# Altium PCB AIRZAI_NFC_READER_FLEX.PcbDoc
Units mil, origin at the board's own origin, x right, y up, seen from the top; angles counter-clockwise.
Board outline 3133.86 x 5807.99 mil, 2 copper layers (Top Layer, Bottom Layer); 43 components, 43 nets, 193 pads, 82 vias.
Unrouted connection lines stored in the file: 129.
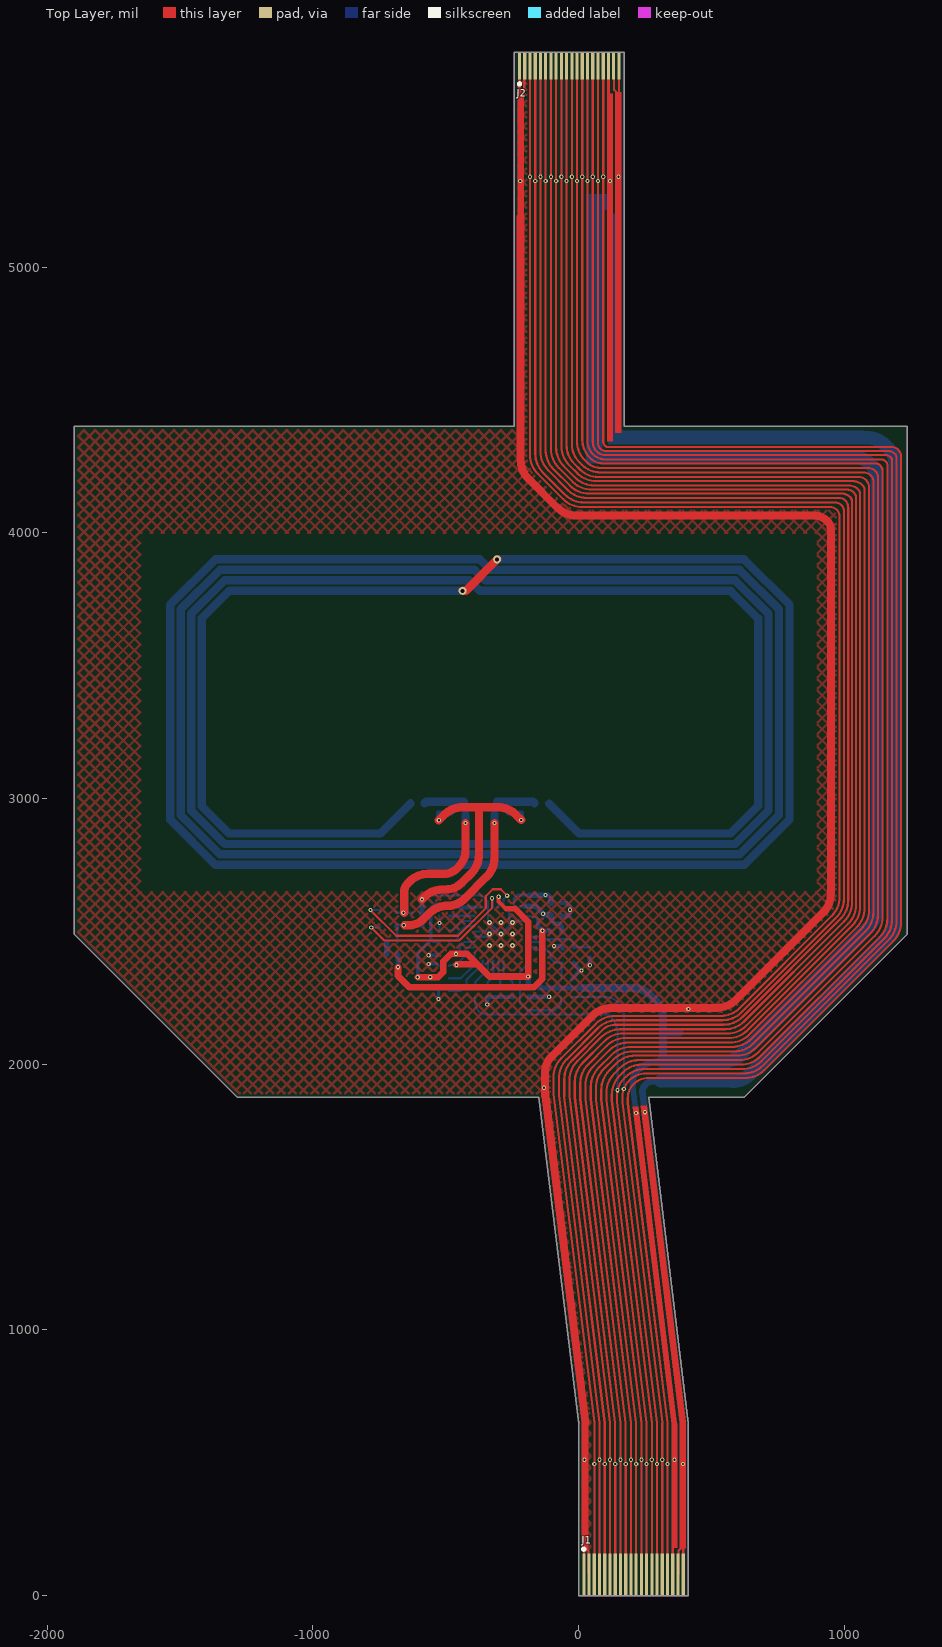
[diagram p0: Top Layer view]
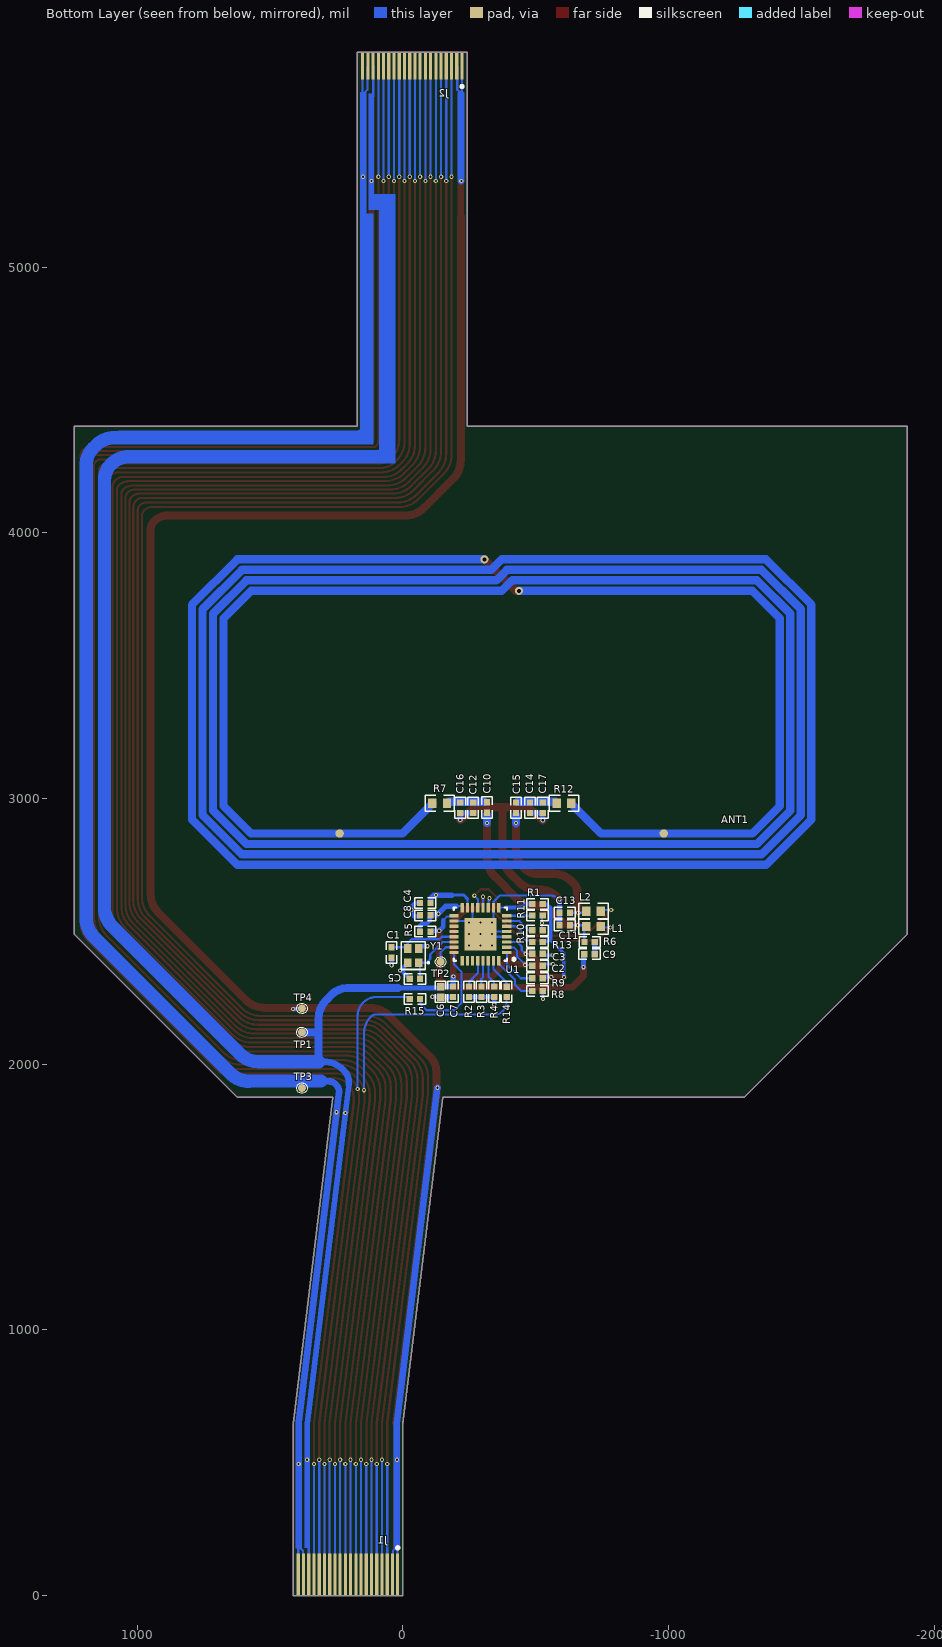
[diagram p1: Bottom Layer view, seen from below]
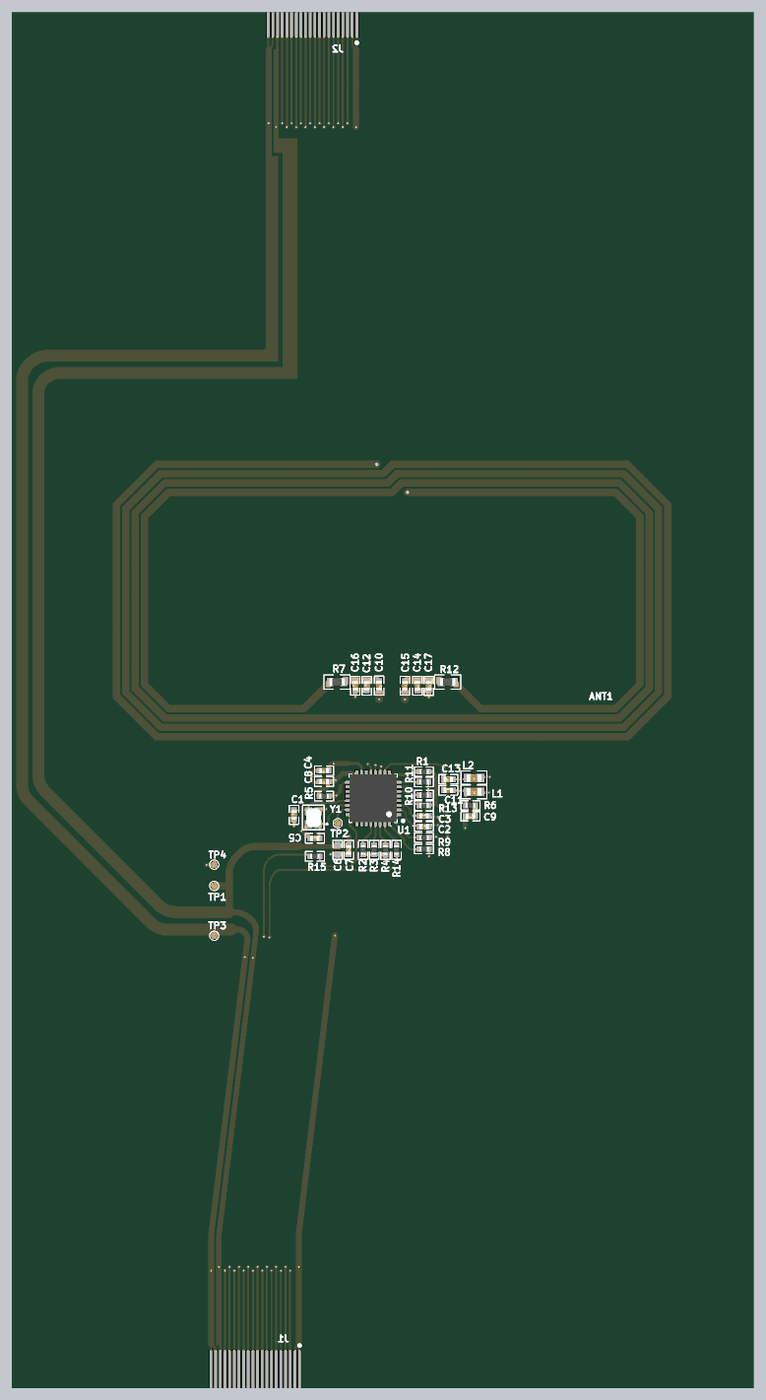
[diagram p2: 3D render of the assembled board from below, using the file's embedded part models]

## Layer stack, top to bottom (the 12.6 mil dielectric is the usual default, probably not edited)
Top Solder: solder mask 0.4, Solder Resist, Dk 3.5
Top Layer: signal copper 1.4
Dielectric 1: dielectric 12.6, FR-4, Dk 4.8
Bottom Layer: signal copper 1.4
Bottom Solder: solder mask 0.4, Solder Resist, Dk 3.5

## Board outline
-1284.09,1874.98 -149.22,1874.98 0,647.51 0,0 413.39,0 413.39,647.51 264.16,1874.98 622.68,1874.98 1236.22,2488.52 1236.22,4401.3 171.26,4401.3 171.26,5807.99 -242.13,5807.99 -242.13,4401.3 -1897.64,4401.3 -1897.64,2649.98 -1897.64,2488.52

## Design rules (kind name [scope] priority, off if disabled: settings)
Clearance Clearance_polygon_5V [OnLayer('Keep-Out Layer') vs (InNet('+5V') AND InPolygon)] p1: gap=10 ignorepadtopadclearanceinfootprint=FALSE
Clearance Clearance_POLYGON_KEEPOUT [(OnLayer('Keep-Out Layer')) vs (InNet('GND') AND InPolygon)] p2: gap=10 ignorepadtopadclearanceinfootprint=FALSE
Clearance [All] p3: gap=6 ignorepadtopadclearanceinfootprint=FALSE
MinimumSolderMaskSliver [All] p1: minsoldermaskwidth=1
PolygonConnect [All] p1: connectstyle=Direct reliefconductorwidth=10 reliefentries=4 polygonreliefangle="90 Angle" airgapwidth=10
RoomDefinition AIRZAI_NFC_READER_FLEX [InComponentClass('AIRZAI_NFC_READER_FLEX')] p1: confinementstyle=ConfineIn formatcopy=TRUE lockcomponents=FALSE outline -17037.88,-12776.19 -2377.88,-12776.19 -2377.88,-3176.19 -17037.88,-3176.19
RoutingVias [All] p1: holewidth=28 width=50 viastyle="Through Hole" minholewidth=8 minwidth=16 maxholewidth=28 maxwidth=50
SilkToSilkClearance [All] p1: silktosilkclearance=1
SilkToSolderMaskClearance [IsPad] p1: minsilkscreentomaskgap=2 clearancetoexposedcopper=TRUE
SolderMaskExpansion [All] p1: expansion=4
UnRoutedNet [All] p1: checkbadconnections=TRUE
Width [All] p1: maxlimit=100 minlimit=6 preferedwidth=10
26 further rules are at their usual default settings.

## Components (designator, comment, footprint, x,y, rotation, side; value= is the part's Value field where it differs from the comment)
ANT1 "NFC_ANT" ANTENNA-NFC-60MMX30MM -371.77,3325.02 r0 bottom
C1 "12pF" 0402CAP 43.03,2420.23 r90 bottom
C2 "0.1µF" 0402CAP -506.62,2370.7 r180 bottom
C3 "0.1µF" 0402CAP -506.62,2415.38 r180 bottom
C4 "0.1µF" 0402CAP -83.95,2606.26 r0 bottom
C5 "12pF" 0402CAP -45.06,2321.09 r180 bottom
C6 "1uF" CAPC0402(1005)60_M -141.75,2272.47 r90 bottom
C7 "0.1µF" 0402CAP -188.97,2272.34 r270 bottom
C8 "0.1µF" 0402CAP -83.95,2560.26 r0 bottom
C9 "1nF" 0402CAP -702.55,2414.09 r0 bottom
C10 "18pF" 0402CAP -316.77,2965.75 r270 bottom
C11 "220pF" 0402CAP -609.12,2523.09 r180 bottom
C12 "47pF" 0402CAP -264.47,2965.32 r90 bottom
C13 "220pF" 0402CAP -609.12,2570.09 r0 bottom
C14 "47pF" 0402CAP -478.47,2965.32 r270 bottom
C15 "18pF" 0402CAP -425.77,2965.32 r270 bottom
C16 "DNP" 0402CAP -215.9,2965.32 r90 bottom
C17 "DNP" 0402CAP -526.47,2965.01 r270 bottom
J1 "FFC Cable" FFC_PADS_MBD 196.85,78.74 r180 top locked
J2 "FFC Cable" FFC_PADS_LID -45.28,5756.81 r180 top locked
L1 "560nH" 0603CAP -717.55,2518.09 r0 bottom
L2 "560mH" 0603CAP -717.55,2576.09 r0 bottom
R1 "0R" 0402 -506.44,2602.57 r180 bottom
R2 "10K" 0402 -248.97,2272.34 r90 bottom
R3 "10K" 0402 -295.97,2272.34 r90 bottom
R4 "10K" 0402 -343.72,2272.34 r90 bottom
R5 "1K" 0402 -84.44,2498.81 r180 bottom
R6 "2.7K" 0402 -702.87,2460.09 r180 bottom
R7 "3.3" 0603 -138.47,2981.32 r180 bottom
R8 "10K" 0402 -506.66,2275.57 r180 bottom
R9 "10K" 0402 -506.66,2323.57 r180 bottom
R10 "0R" 0402 -506.63,2503.57 r180 bottom
R11 "0R" 0402 -506.44,2559.57 r180 bottom
R12 "3.3" 0603 -606.47,2981.32 r0 bottom
R13 "10K" 0402 -506.44,2459.57 r180 bottom
R14 "0R" 0402 -390.4,2272.23 r270 bottom
R15 "0R" 0402 -45.06,2245.2 r0 bottom
TP1 "WIREPT" TP_0.9MM 380,2120 r90 bottom
TP2 "WIREPT" TP_0.9MM -141.97,2385.09 r90 bottom
TP3 "WIREPT" TP_0.9MM 380,1910 r90 bottom
TP4 "WIREPT" TP_0.9MM 380,2210 r90 bottom
U1 "MFRC52202HN1,115" VFQFN-32-MFRC52202HN1,157 -291.95,2489.54 r0 bottom
Y1 "27.12MHz" XTAL_2016 -38.95,2408.23 r90 bottom

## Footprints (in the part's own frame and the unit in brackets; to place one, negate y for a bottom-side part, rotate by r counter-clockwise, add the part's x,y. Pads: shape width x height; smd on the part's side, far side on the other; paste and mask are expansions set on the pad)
0402 [mm] "Chip Resistor, Body 1.1x0.5mm, IPC High Density"
  rect 0.6x0.6 smd: 1(-0.5,0) 2(0.5,0)
  silkscreen extent -1.02,-0.51 1.02,0.51, body extent -0.5,-0.25 0.5,0.25, height 0.27
0402CAP [mm] "Chip Capacitor, Body 1.1x0.5mm, IPC High Density"
  rect 0.6x0.6 smd: 1(-0.5,0) 2(0.5,0)
  silkscreen extent -1.02,-0.51 1.02,0.51, body extent -0.5,-0.3 0.5,0.3, height 0.19
0603 [mm] "Chip Resistor, Body 1.6x0.8mm, IPC High Density"
  rect 0.8x0.9 smd: 1(-0.7,0) 2(0.7,0)
  silkscreen extent -1.4,-0.76 1.4,0.76, body extent -0.8,-0.41 0.8,0.4, height 0.37
0603CAP [mm] "Chip Capacitor, Body 1.6x0.8mm, IPC High Density"
  rect 0.8x0.9 smd: 1(-0.7,0) 2(0.7,0)
  silkscreen extent -1.4,-0.76 1.4,0.76, body extent -0.8,-0.4 0.8,0.4, height 0.29
ANTENNA-NFC-60MMX30MM [mil] "ANTENNA-ID2+10P-01"
  round 30 hole 15: 1(-65,-456.69) 2(65,-574.8)
  round 31.5 smd paste-31.5: 1(610,456.69) 2(-610,456.69)
  Top Layer lines w31.5: -610,456.69 -943.7,456.69 -1047.24,353.15 -1047.24,-353.15 -943.7,-456.69 -65,-456.69 ; 65,-574.8 994.96,-574.8 1165.35,-404.41 1165.35,404.41 994.96,574.8 -994.96,574.8 -1165.35,404.41 -1165.35,-404.41 -994.96,-574.8 0,-574.8 39.37,-535.43 977.87,-535.43 1125.98,-387.32 1125.98,387.32 977.87,535.43 -977.87,535.43 -1125.98,387.32 -1125.98,-387.32 -977.87,-535.43 -19.37,-535.43 20,-496.06 960.79,-496.06 1086.61,-370.24 1086.61,370.24 960.79,496.06 -960.79,496.06 -1086.61,370.24 -1086.61,-370.24 -960.79,-496.06 -39.37,-496.06 0,-456.69 943.7,-456.69 1047.24,-353.15 1047.24,353.15 943.7,456.69 610,456.69
  Bottom Layer lines w31.5: -65,-456.69 -53.11,-456.69 65,-574.8
CAPC0402(1005)60_M [mm] "Chip Capacitor, Body 1.0x0.5mm, Height 0.6mm, IPC Low Density"
  rect 0.72x0.72 smd: 1(-0.5,0) 2(0.5,0)
  silkscreen extent -1.02,-0.51 1.02,0.51, body extent -0.55,-0.3 0.55,0.3, height 0.6
FFC_PADS_LID [mm] "(0.50mm"
  rect 0.3x2.6 smd: 1(4.5,0) 2(4,0) 3(3.5,0) 4(3,0) 5(2.5,0) 6(2,0) 7(1.5,0) 8(1,0) 9(0.5,0) 10(0,0) 11(-0.5,0) 12(-1,0) 13(-1.5,0) 14(-2,0) 15(-2.5,0) 16(-3,0) 17(-3.5,0) 18(-4,0) 19(-4.5,0) 20(-5,0)
  rect 0.3x2.6 smd far side: 1(4.5,0) 2(4,0) 3(3.5,0) 4(3,0) 5(2.5,0) 6(2,0) 7(1.5,0) 8(1,0) 9(0.5,0) 10(0,0) 11(-0.5,0) 12(-1,0) 13(-1.5,0) 14(-2,0) 15(-2.5,0) 16(-3,0) 17(-3.5,0) 18(-4,0) 19(-4.5,0) 20(-5,0)
  silkscreen extent 4.37,1.58 4.62,1.83
FFC_PADS_MBD [mm] "(0.50mm"
  rect 0.3x4 smd: 1(4.5,0) 2(4,0) 3(3.5,0) 4(3,0) 5(2.5,0) 6(2,0) 7(1.5,0) 8(1,0) 9(0.5,0) 10(0,0) 11(-0.5,0) 12(-1,0) 13(-1.5,0) 14(-2,0) 15(-2.5,0) 16(-3,0) 17(-3.5,0) 18(-4,0) 19(-4.5,0) 20(-5,0)
  rect 0.3x4 smd far side: 1(4.5,0) 2(4,0) 3(3.5,0) 4(3,0) 5(2.5,0) 6(2,0) 7(1.5,0) 8(1,0) 9(0.5,0) 10(0,0) 11(-0.5,0) 12(-1,0) 13(-1.5,0) 14(-2,0) 15(-2.5,0) 16(-3,0) 17(-3.5,0) 18(-4,0) 19(-4.5,0) 20(-5,0)
  silkscreen extent 4.39,-2.56 4.64,-2.31
TP_0.9MM [mm] "0.9MM DIA TESTPOINT"
  round 0.75 smd paste-5 mask+0.05: 1(0,0)
  silkscreen extent -0.5,-0.5 0.5,0.5
VFQFN-32-MFRC52202HN1,157 [mm]
  rect 0.9x0.31 smd: 1(-2.529,1.75) 2(-2.529,1.25) 3(-2.529,0.75) 4(-2.529,0.25) 5(-2.529,-0.25) 6(-2.529,-0.75) 7(-2.529,-1.25) 8(-2.529,-1.75) 17(2.529,-1.75) 18(2.529,-1.25) 19(2.529,-0.75) 20(2.529,-0.25) 21(2.529,0.25) 22(2.529,0.75) 23(2.529,1.25) 24(2.529,1.75)
  rect 0.31x0.9 smd: 9(-1.75,-2.529) 10(-1.25,-2.529) 11(-0.75,-2.529) 12(-0.25,-2.529) 13(0.25,-2.529) 14(0.75,-2.529) 15(1.25,-2.529) 16(1.75,-2.529) 25(1.75,2.529) 26(1.25,2.529) 27(0.75,2.529) 28(0.25,2.529) 29(-0.25,2.529) 30(-0.75,2.529) 31(-1.25,2.529) 32(-1.75,2.529)
  rect 3.1x3.1 smd: 33(0,0)
  silkscreen extent -3.32,-2.55 2.55,2.55, body extent -2.55,-2.55 2.55,2.55, height 1
XTAL_2016 [mm] "2.00mm x 1.60mm"
  rect 0.85x0.75 smd: 1(-0.675,-0.525) 2(0.675,-0.525) 3(0.675,0.525) 4(-0.675,0.525)
  silkscreen extent -1.32,-1.47 1.32,1.14, body extent -1,-0.81 1,0.79, height 0.65

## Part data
C1 C5: library part CAP, "CAP CER 12PF 50V C0G/NP0 0402", Case/Package=0402, Case Code (Metric)=1005, Dielectric=C0G, Dielectric Material=Ceramic, Manufacturer=KEMET, Manufacturer Part Number=C0402C120J5GACTU, Max Operating Temperature=125°C, Min Operating Temperature=-55°C, Package Quantity=1, Supplier Part Number 1=399-1013-6-ND, Temperature Coefficient=30ppm/°C, Tolerance=5%, Voltage=50V
C2 C3 C4 C7 C8: library part C0402-100n, "Capacitor, X7R, ±10%", Case-EIA=0402, Case-Metric=1005, Manufacturer=TDK, Manufacturer Part Number=C1005X7R1C104K, Rated Voltage="16 V", Supplier Part Number 1=445-4952-2-ND, Tolerance=±20%
C6: library part CAP, "CAP 1uF 16V ±10% 0402 (1005 Metric) Thickness 0.6mm SMD", Case/Package=0402, Case Code (Metric)=1005, Dielectric=X5R, Manufacturer="Taiyo Yuden", Manufacturer Part Number=EMK105BJ105KV-F, Max Operating Temperature=85°C, Min Operating Temperature=-55°C, Package Quantity=1, Supplier Part Number 1=587-2477-6-ND, Tolerance=10%, Voltage Rating=16V
C9: library part 56p, "CAP CER 1000PF 50V C0G/NP0 0402", Case/Package=0402, Case Code (Metric)=1005, Dielectric=C0G, Manufacturer=Murata, Manufacturer Part Number=GRM1555C1H102FA01D, Max Operating Temperature=125°C, Min Operating Temperature=-55°C, Package Quantity=1, Supplier Part Number 1=490-6189-1-ND, Tolerance=1%, Voltage=50V
C10 C15: library part 56p, "CAP CER 18PF 50V NP0 0402", Case/Package=0402, Case Code (Metric)=1005, Dielectric=C0G, Manufacturer="Kyocera AVX", Manufacturer Part Number=04025U180FAT2A, Max Operating Temperature=125°C, Min Operating Temperature=-55°C, Package Quantity=10000, Supplier Part Number 1=478-10144-1-ND, Tolerance=1%, Voltage Rating=50V
C11 C13: library part 56p, "CAP CER 220PF 50V NPO 0402", Case/Package=0402, Case Code (Metric)=1005, Dielectric=C0G, Manufacturer=Yageo, Manufacturer Part Number=CC0402FRNPO9BN221, Max Operating Temperature=125°C, Min Operating Temperature=-55°C, Supplier Part Number 1=311-3730-1-ND, Tolerance=1%, Voltage Rating=50V
C12 C14: library part 56p, "CAP CER 47PF 50V C0G/NP0 0402", Dielectric=C0G, Manufacturer=Murata, Manufacturer Part Number=GJM1555C1H470FB01D, Supplier Part Number 1=490-16376-1-ND, Tolerance=1%, Voltage Rating (DC)=50V
C16 C17: library part 56p
J1 J2: library part XF2M-2015-1A-R100, "Cable"
L1: library part Inductor, "FIXED IND 560NH 100MA 1.05 OHM", Case/Package=0603, Case Code (Metric)=1608, Current Rating=100mA, DC Resistance (DCR)=1.05R, Manufacturer=TDK, Manufacturer Part Number=MLF1608DR56JTD25, Max DC Current=30mA, Max Operating Temperature=125°C, Min Operating Temperature=-55°C, Package Quantity=4000, Ratings=AEC-Q200, Self Resonant Frequency=170MHz, Supplier Part Number 1=445-16970-1-ND, Test Frequency=25MHz, Tolerance=5%
L2: library part Inductor, "FIXED IND 560NH 100MA 1.05 OHM", Case/Package=0603, Case Code (Metric)=1608, Current Rating=100mA, DC Resistance (DCR)=1.05R, Inductance=560nH, Manufacturer=TDK, Manufacturer Part Number=MLF1608DR56JTD25, Max DC Current=30mA, Max Operating Temperature=125°C, Min Operating Temperature=-55°C, Package Quantity=4000, Ratings=AEC-Q200, Self Resonant Frequency=170MHz, Supplier Part Number 1=445-16970-1-ND, Test Frequency=25MHz, Tolerance=5%
R1 R10 R11 R14 R15: library part R0402-12k, "Resistor, ±1%, 0.063W", Case-EIA=0402, Case-Metric=1005, Manufacturer=Panasonic, Manufacturer Part Number=ERJ-2GE0R00X, Supplier Part Number 1=P0.0JTR-ND, Tolerance=±5%
R2 R3 R4 R8 R9 R13: library part R0402-12k, "Resistor 10K, ±1%, 0.063W", Case/Package=0402, Case Code (Metric)=1005, Manufacturer="Vishay Dale", Manufacturer Part Number=CRCW040210K0JNED, Max Operating Temperature=155°C, Max Power Dissipation=63mW, Min Operating Temperature=-55°C, Package Quantity=1, Resistance=10kR, Supplier Part Number 1=541-10KJDKR-ND, Temperature Coefficient=200ppm/°C, Tolerance=5%, Voltage Rating=50V
R5: library part R0402-12k, "RES SMD 1K OHM 1% 1/16W 0402", Case/Package=0402, Case Code (Metric)=1005, Manufacturer=Yageo, Manufacturer Part Number=RC0402FR-071KL, Max Operating Temperature=155°C, Min Operating Temperature=-55°C, Power Rating=62.5mW, Resistance=1kR, Supplier Part Number 1=311-1.00KLRCT-ND, Temperature Coefficient=100ppm/°C, Tolerance=1%, Voltage Rating=50V
R6: library part R0402-12k, "RES SMD 2.7K OHM 1% 1/16W 0402", Case/Package=0402, Manufacturer="Yageo Phycomp", Manufacturer Part Number=RC0402FR-072K7L, Max Operating Temperature=155°C, Min Operating Temperature=-55°C, Power Rating=63mW, Resistance=2.7kR, Supplier Part Number 1=311-2.70KLRCT-ND, Temperature Coefficient=100ppm/°C, Tolerance=1%, Voltage Rating (DC)=50V
R7 R12: library part R0402-12k, "RES SMD 3.3 OHM 1% 1/10W 0603", Case/Package=0603, Manufacturer=Yageo, Manufacturer Part Number=AC0603FR-073R3L, Max Operating Temperature=155°C, Max Power Dissipation=100mW, Min Operating Temperature=-55°C, Resistance=3.3R, Supplier Part Number 1=YAG5335CT-ND, Temperature Coefficient=200ppm/°C, Tolerance=1%
U1: library part MFRC52201HN1,157, "IC RFID READER 13.56MHZ 32HVQFN", Frequency=13.56MHz, Manufacturer="NXP Semiconductors", Max Operating Temperature=85°C, Min Operating Temperature=-25°C, Package Quantity=1500, Supplier Part Number 1=568-15200-1-ND
Y1: library part ZTB_2, "CRYSTAL 27.12MHZ 10PF SMD", Manufacturer="ECS International", Manufacturer Part Number=ECS-271.2-10-37-CKM-TR, Supplier Part Number 1=XC2511DKR-ND

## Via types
v1: diameter 16, hole 8, Top Layer to Bottom Layer, tented both sides, 73 vias
v2: diameter 19.68, hole 8, Top Layer to Bottom Layer, 9 vias

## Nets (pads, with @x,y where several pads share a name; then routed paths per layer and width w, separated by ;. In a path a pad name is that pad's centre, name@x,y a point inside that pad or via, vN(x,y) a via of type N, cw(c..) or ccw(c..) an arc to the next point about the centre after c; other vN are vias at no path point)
3V3: C2.1 C3.1 C4.1 C6.2 C7.1 J1.18 J2.18 R1.2 R9.2 R13.2 TP1.1 U1.2 U1.3 U1.12 U1.15 | length 6922
  Top Layer w10: 112.1,5644.23 112.2,5644.33 J2.18@112.2,5756.81 ; 354.23,191.32 354.33,191.22 J1.18@354.33,78.74
  Top Layer w15: v1(-301.02,2630.32) -301.02,2612.57 -273.23,2584.78
  Top Layer w20: -273.23,2584.78 -238.41,2584.78
  Top Layer w25: v1@-606,2327.59 -528.25,2327.59 -509.44,2346.39 -509.44,2386.44 -480.5,2415.38 v1(-461.44,2415.38) -420.42,2415.38 -380.52,2375.48 ; v1(-459.94,2373.88) -458.34,2375.48 -380.52,2375.48 ; -238.41,2584.78 -189.97,2536.34 v1(-189.97,2329.78) -334.83,2329.78 -380.52,2375.48
  Bottom Layer w8: C2.1 -483.76,2373.88 v1(-459.94,2373.88) -429.97,2403.84 -429.97,2427.09 -417.24,2439.82 -392.02,2439.82 U1.2 ; C3.1 v1(-461.44,2415.38) -447.44,2429.38 -447.44,2443.09 -430.51,2460.01 U1.3 ; U1.12 -301.02,2589.88 v1(-301.02,2630.32) ; U1.15 -242.74,2620.78
  Bottom Layer w10: 112.1,5644.23 112.2,5644.33 J2.18@112.2,5756.81 ; 354.23,191.32 354.33,191.22 J1.18@354.33,78.74
  Bottom Layer w12: -242.74,2620.78 -242.74,2623.02 -228.97,2636.78 -183.97,2636.78
  Bottom Layer w13: v1(-606,2327) -606,2417 -556.77,2466.23 -556.77,2471.32 ; R13.2 -528.87,2462.32 -547.77,2462.32 -556.77,2471.32 ; R1.2 -541.87,2602.57 -556.77,2587.67 -556.77,2471.32
  Bottom Layer w15: v1(-558.44,2327.59) -530.36,2327.59 R9.2
  Bottom Layer w20: v1(-189.97,2329.78) -189.97,2293.03 C7.1 -141.88,2292.03 C6.2 ; -183.97,2636.78 -183.58,2636.39 -116.44,2636.39 -104.44,2624.39 -104.44,2607.06 C4.1
  Bottom Layer w25: 203.23,1922.32 203.23,1931.87 cw(c264.68,1931.87) 221.23,1975.32 225.94,1980.03 cw(c296.65,1909.32) 296.65,2009.32 317.23,2009.32
  Bottom Layer w30: 19,2286.32 209.28,2286.32 cw(c209.28,2203.28) 268,2262 287.94,2242.06 cw(c217.23,2171.35) 317.23,2171.35 317.23,2117 ; 317.23,2009.32 317.23,2117 ; TP1.1 320.23,2120 317.23,2117
  Bottom Layer w50: 57.23,4286.32 1029.22,4286.32 cw(c1029.22,4187.31) 1099.23,4257.32 cw(c1041.29,4199.38) 1123.23,4199.38 1123.23,2589.74 cw(c1023.23,2589.74) 1093.94,2519.03 613.52,2038.61 cw(c542.81,2109.32) 542.81,2009.32 317.23,2009.32
  other v1: 360.43,511.32 216.54,1816.32 -124.83,2636.39 118.3,5324.23
+5: J1.19 J1.20 J2.19 J2.20 TP3.1 | length 4943.7
  Top Layer w8: J2.19@131.89,5756.81 133.67,5755.03 133.67,5667.13 151.57,5649.23 J2.20@151.57,5756.81 ; J1.19@374.02,78.74 375.8,80.52 375.8,168.42 393.7,186.32 J1.20@393.7,78.74
  Bottom Layer w8: J2.19@131.89,5756.81 133.67,5755.03 133.67,5667.13 151.57,5649.23 J2.20@151.57,5756.81 ; J1.19@374.02,78.74 375.8,80.52 375.8,168.42 393.7,186.32 J1.20@393.7,78.74
  Bottom Layer w25: 239.23,1892.32 cw(c282.68,1892.32) 251.96,1923.05 254.23,1925.32 cw(c278.37,1901.18) 278.37,1935.32 309.23,1936.32
  Bottom Layer w40: 155.1,4371.32 ccw(c186.49,4402.71) 186.49,4358.32 ; 1155.52,4329.03 1165.23,4319.32
  Bottom Layer w50: 186.49,4358.32 1084.81,4358.32 cw(c1084.81,4258.32) 1155.52,4329.03 ; 309.23,1936.32 577.81,1935.32 ccw(c577.81,2035.32) 648.52,1964.61 1162.94,2479.03 ccw(c1092.23,2549.74) 1192.23,2549.74 1192.23,4254.14 ccw(c1100.04,4254.14) 1165.23,4319.32
  other v1: 392.43,495.32 250.23,1819.32 150.3,5340.23
ACCELERO_INT: J1.14 J2.14 | length 8322.1
  Top Layer w8: J2.14@33.46,5756.81 33.46,4345.45 ccw(c104.36,4345.45) 54.23,4295.32 ccw(c100.1,4341.19) 100.1,4276.32 1136.91,4276.32 cw(c1136.91,4249.01) 1156.23,4268.32 cw(c1141.74,4253.84) 1162.23,4253.84 1162.23,4098.32 1162.23,2548.74 cw(c1062.23,2548.74) 1132.94,2478.03 682.52,2027.61 cw(c611.81,2098.32) 611.81,1998.32 237.65,1998.32 ccw(c237.65,1898.32) 166.94,1969.03 154.13,1956.22 ccw(c224.84,1885.51) 124.84,1885.51 124.84,1864.77 275.59,649.15 J1.14@275.59,78.74
  Bottom Layer w8: v1@33.46,5324.23 J2.14@33.46,5756.81 ; J1.14@275.59,78.74 v1@275.59,511.32
  other v1: 275.23,511.32 33.1,5324.23
ADC_CH1: J1.5 J2.5 | length 8284.9
  Top Layer w8: J2.5@-143.7,5756.81 -143.7,4305.67 ccw(c-43.7,4305.67) -114.41,4234.96 -40.06,4160.61 ccw(c30.65,4231.32) 30.65,4131.32 981.5,4131.32 cw(c981.5,4100.59) 1003.23,4122.32 cw(c974.96,4094.05) 1014.94,4094.05 1014.94,4039.32 1014.94,2617.45 cw(c914.94,2617.45) 985.65,2546.74 616.52,2177.61 cw(c545.81,2248.32) 545.81,2148.32 136.1,2148.32 ccw(c136.1,2083.45) 90.23,2129.32 -25.05,2014.05 ccw(c45.67,1943.34) -54.33,1943.34 -54.33,1879.38 98.23,649.15 v1(98.23,495.32) ; J1.5@98.43,78.74 v1@98.43,495.32
  Bottom Layer w8: v1@-143.7,5340.23 J2.5@-143.7,5756.81 ; J1.5@98.43,78.74 v1@98.43,495.32
  other v1: -143.9,5340.23
CAP1_TOUCH_OUT: J1.7 J2.7 | length 8281.2
  Top Layer w8: J2.7@-104.33,5756.81 v1(-104.33,5340.23) -104.33,4315.3 ccw(c-4.33,4315.3) -75.04,4244.59 -22.06,4191.61 ccw(c48.65,4262.32) 48.65,4162.32 1009.67,4162.32 cw(c1009.67,4124.77) 1036.23,4151.32 cw(c1016.91,4132.01) 1044.23,4132.01 1044.23,4098.32 1044.23,2599.74 cw(c944.23,2599.74) 1014.94,2529.03 630.52,2144.61 cw(c559.81,2215.32) 559.81,2115.32 167.27,2115.32 ccw(c167.27,2015.32) 96.56,2086.03 14.68,2004.16 ccw(c85.39,1933.45) -14.61,1933.45 -14.61,1876.49 137.6,649.15 v1@137.6,495.32 ; J1.7@137.8,78.74 v1(137.8,495.32)
  Bottom Layer w8: v1(-104.33,5340.23) J2.7@-104.33,5756.81 ; J1.7@137.8,78.74 v1(137.8,495.32)
CAP2_TOUCH_OUT: J1.8 J2.8 | length 8307
  Top Layer w8: J2.8@-84.65,5756.81 v1(-84.65,5324.23) -84.65,4321.62 ccw(c15.35,4321.62) -55.36,4250.91 -12.06,4207.61 ccw(c58.65,4278.32) 58.65,4178.32 1016.02,4178.32 cw(c1016.02,4127.11) 1052.23,4163.32 cw(c1035.33,4146.42) 1059.23,4146.42 1059.23,4098.32 1059.23,2592.74 cw(c959.23,2592.74) 1029.94,2522.03 635.52,2127.61 cw(c564.81,2198.32) 564.81,2098.32 176.65,2098.32 ccw(c176.65,1998.32) 105.94,2069.03 35.27,1998.36 ccw(c105.98,1927.65) 5.98,1927.65 5.98,1870.81 157.48,649.15 v1(157.48,511.32) J1.8@157.48,78.74
  Bottom Layer w8: v1(-84.65,5324.23) J2.8@-84.65,5756.81 ; J1.8@157.48,78.74 v1(157.48,511.32)
EN: J1.17 J2.17 | length 8285.8
  Top Layer w8: J2.17@92.52,5756.81 v1(92.52,5340.23) 92.52,4344.93 ccw(c118.84,4344.93) 100.21,4326.34 ccw(c107.47,4333.57) 107.47,4323.32 1178.09,4323.32 cw(c1178.09,4289.18) 1202.23,4313.32 cw(c1175.67,4286.77) 1213.23,4286.77 1213.23,4098.32 1213.23,2533.74 cw(c1113.23,2533.74) 1183.94,2463.03 698.52,1977.61 cw(c627.81,2048.32) 627.81,1948.32 264.17,1948.32 ccw(c264.17,1866.38) 206.23,1924.32 ccw(c257.71,1872.84) 184.9,1872.84 184.9,1855.03 334.45,649.15 v1@334.45,495.32 ; J1.17@334.65,78.74 v1(334.65,495.32)
  Bottom Layer w8: v1(92.52,5340.23) J2.17@92.52,5756.81 ; J1.17@334.65,78.74 v1(334.65,495.32)
GND: C1.1 C2.2 C3.2 C4.2 C5.1 C6.1 C7.2 C8.2 C11.1 C12.1 C13.2 C14.2 C16.1 C17.2 J1.1 J1.2 J2.1 J2.2 R2.1 R3.1 R4.1 R8.2 R10.2 R11.2 TP4.1 U1.4 U1.5 U1.10 U1.14 U1.18 U1.33 Y1.2 Y1.4 | length 11361.9
  Top Layer w8: -222.44,5649.23 J2.1@-222.44,5756.81 ; -218.01,5653.66 -204.54,5667.13 J2.2@-204.54,5755.03 ; J1.1@19.69,78.74 19.69,186.32 ; 24.11,181.89 37.59,168.42 J1.2@37.59,80.52
  Top Layer w25: -218.01,5189.23 -218.01,5653.66 ; 24.11,181.89 24.11,646.32
  Top Layer w30: -218.01,5189.23 -218.01,4273.98 ccw(c-118.01,4273.98) -188.72,4203.27 -80.06,4094.61 ccw(c-9.35,4165.32) -9.35,4065.32 884.12,4065.32 cw(c884.12,3990.21) 937.23,4043.32 cw(c908.26,4014.35) 949.23,4014.35 949.23,3977.32 949.23,2640.74 cw(c849.23,2640.74) 919.94,2570.03 591.52,2241.61 cw(c520.81,2312.32) 520.81,2212.32 123.65,2212.32 ccw(c123.65,2112.32) 52.94,2183.03 -103.14,2026.95 ccw(c-48.52,1972.32) -125.77,1972.32 -125.77,1881.79 ccw(c-122.36,1881.79) -124.77,1879.38
  Top Layer w31.5: v1(-589.44,2620.32) -580.54,2629.22 cw(c-512.69,2561.36) -512.69,2657.32 -501.54,2657.32 ccw(c-501.54,2746.09) -438.77,2683.32 -404.06,2718.03 ccw(c-474.77,2788.74) -374.77,2788.74 -374.77,2967.32 ; v1(-526.2,2918.32) -506.48,2938.03 cw(c-435.77,2867.32) -435.77,2967.32 ; -440.77,2967.32 -374.77,2967.32 ; v1(-215.9,2918.91) -235.03,2938.03 ccw(c-305.74,2867.32) -305.74,2967.32 -374.77,2967.32
  Bottom Layer w8: v1(-589.44,2620.32) cw(c-555.64,2586.52) -555.64,2634.32 -363.74,2634.32 -341.16,2611.75 U1.10 -341.16,2538.75 v2(-335.26,2532.85) U1.33@-301.79,2499.38 ; C2.2@-532.84,2377.23 C2.2 ; C3.2@-531.6,2410.09 C3.2 ; R10.2 ccw(c-532.44,2509.7) -523.77,2509.7 v1(-523.77,2531.32) -523.77,2557.22 R11.2 ; U1.4 U1.33@-335.26,2479.7 ; U1.5 U1.33@-301.79,2499.38 ; U1.14 -262.42,2546.56 v2(-248.65,2532.85) v2(-248.65,2532.85) ; -222.44,5649.23 J2.1@-222.44,5756.81 ; -218.9,5652.77 -204.54,5667.13 J2.2@-204.54,5755.03 ; U1.18 -242.74,2538.75 v2(-248.65,2532.85) ; J1.1@19.69,78.74 19.69,186.32 ; 23.23,182.78 37.59,168.42 J1.2@37.59,80.52 ; U1.33@-301.79,2499.38 v2(-291.95,2489.54) v2(-248.65,2532.85)
  Bottom Layer w12: v1@-558.44,2377.23 C2.2@-532.84,2377.23 ; v1@-558.44,2410.09 C3.2@-531.6,2410.09 ; v1(-527.44,2245.09) -527.44,2274.48 R8.2
  Bottom Layer w15: TP4.1 381.81,2208.19 412.81,2208.19 v1(413,2208)
  Bottom Layer w16: v1(-343.72,2224.88) R4.1 R3.1 R2.1 ; v1(-92.77,2444.32) -91.98,2443.53 -66.4,2443.53 -59.64,2436.77 Y1.2 ; C8.2 -60.96,2556.95 -42.14,2556.95 -32.77,2566.32 v1(-32.77,2581.32) -32.77,2593.31 -45.72,2606.26 C4.2 ; C5.1 5.76,2352.23 9.19,2352.23 -18.27,2379.68 Y1.4 ; v1(42.23,2372.32) 42.23,2399.74 C1.1
  Bottom Layer w18: R2.1 R2.1@-248.91,2252.72 ; C7.2 -188.91,2252.72 -141.81,2252.72 C6.1 -140.53,2254 v1(-110.91,2254)
  Bottom Layer w20: C11.1 C13.2 v1(-589.44,2620.32) ; v1(-526.2,2918.32) -526.2,2945.05 C17.2 -526.31,2945.48 -478.62,2945.48 C14.2 ; C12.1 C16.1 v1(-215.9,2918.91)
  Bottom Layer w25: v1@-218.9,5324.23 -218.9,5652.77 ; v1(-130,1911.11) 23.23,646.32 23.23,182.78
  other v1: 22.23,511.32 11.05,2352.23 -564.44,2377.23 -564.44,2410.09 -219.9,5324.23
  other v2: -335.26,2446.23 -291.95,2446.23 -248.65,2446.23 -335.26,2489.54 -248.65,2489.54 -291.95,2532.85
"LED Str CLK": J1.10 J2.10 | length 8309.6
  Top Layer w8: J2.10@-45.28,5756.81 v1(-45.28,5324.23) -45.28,4330.25 ccw(c54.72,4330.25) -15.99,4259.54 5.23,4238.32 ccw(c72.83,4305.92) 72.83,4210.32 1054.67,4210.32 cw(c1054.67,4172.77) 1081.23,4199.32 cw(c1052.26,4170.35) 1093.23,4170.35 1093.23,4144.32 1093.23,2579.74 cw(c993.23,2579.74) 1063.94,2509.03 649.52,2094.61 cw(c578.81,2165.32) 578.81,2065.32 195.65,2065.32 ccw(c195.65,1965.32) 124.94,2036.03 74.85,1985.94 ccw(c145.56,1915.23) 45.56,1915.23 45.56,1869.12 196.85,649.15 v1(196.85,511.32) J1.10@196.85,78.74
  Bottom Layer w8: v1(-45.28,5324.23) J2.10@-45.28,5756.81 ; J1.10@196.85,78.74 v1(196.85,511.32)
"LED Str DATA": J1.11 J2.11 | length 8281.2
  Top Layer w8: J2.11@-25.59,5756.81 v1(-25.59,5340.23) -25.59,4333.48 ccw(c69.39,4333.48) 2.23,4266.32 11.94,4256.61 ccw(c82.65,4327.32) 82.65,4227.32 1071.26,4227.32 cw(c1071.26,4186.35) 1100.23,4215.32 cw(c1078.5,4193.59) 1109.23,4193.59 1109.23,4098.32 1109.23,2570.74 cw(c1009.23,2570.74) 1079.94,2500.03 657.52,2077.61 cw(c586.81,2148.32) 586.81,2048.32 202.65,2048.32 ccw(c202.65,1948.32) 131.94,2019.03 94.73,1981.82 ccw(c165.44,1911.11) 65.44,1911.11 65.44,1865.98 216.34,649.15 v1@216.34,495.32 ; J1.11@216.54,78.74 v1(216.54,495.32)
  Bottom Layer w8: v1(-25.59,5340.23) J2.11@-25.59,5756.81 ; J1.11@216.54,78.74 v1(216.54,495.32)
NetANT1_1: ANT1.1 R7.1 | length 406.9
  Bottom Layer w31.5: R7.1 2.09,2868.32 238.23,2868.32 ANT1.1@249.23,2868.32
NetANT1_2: ANT1.2 R12.1 | length 421.7
  Bottom Layer w31.5: -1005.77,2868.32 -981.77,2868.32 -746.18,2868.32 R12.1@-632.96,2981.54 ; R12.1@-634.03,2979.35 R12.1
NetC1_2: C1.2 U1.21 Y1.3 | length 268.4
  Bottom Layer w8: U1.21 -147,2479.7 -137.3,2470 -32.52,2470 -18.27,2455.75 Y1.3 -13.16,2439.91 C1.2
NetC5_2: C5.2 U1.22 Y1.1 | length 236.2
  Bottom Layer w8: U1.22 -150.28,2460.01 -102.97,2412.71 -102.97,2395.78 -88.97,2381.78 -59.77,2381.78 Y1.1 -64.97,2376.31 C5.2@-64.97,2322.78
NetC9_1: C9.1 R6.2 | length 46.1
  Bottom Layer w20: R6.2 -722.24,2459.77 C9.1
NetC9_2: C9.2 R5.2 U1.17 | length 964.5
  Top Layer w25: v1(-679.78,2365.21) -679.78,2332.21 -636.78,2289.21 -168.78,2289.21 -136.62,2321.38 v1(-136.62,2502.12)
  Bottom Layer w8: U1.17 -190.28,2556.34 -167.22,2556.34 -151.97,2541.09
  Bottom Layer w17: -151.97,2541.09 -151.97,2517.48 v1(-136.62,2502.12) -107.43,2502.12 R5.2
  Bottom Layer w20: C9.2 C9.2@-681.06,2412.28 ; v1(-679.78,2365.21) C9.2@-679.78,2412.28
NetC10_1: C10.1 C12.2 C16.2 R7.2 | length 143.8
  Bottom Layer w31.5: C10.1@-307.16,2987.32 R7.2@-173.03,2987.32 ; R7.2@-172.03,2987.32 -168,2983.29 -166.03,2983.29 R7.2
NetC10_2: C10.2 C11.2 L1.2 R6.1 | length 742.3
  Top Layer w31.5: v1@-655.4,2523.09 -639.39,2523.09 ccw(c-639.39,2601.26) -584.11,2545.98 -563.06,2567.03 cw(c-492.35,2496.32) -492.35,2596.32 ccw(c-492.35,2684.63) -429.91,2622.19 -346.06,2706.04 ccw(c-416.77,2776.75) -316.77,2776.75 v1(-316.77,2907.75)
  Bottom Layer w10: R6.1 -683.18,2511.28 L1.2 -684.99,2523.09 v1(-658.4,2523.09) C11.2 C11.2@-625.81,2523.09
  Bottom Layer w31.5: v1(-316.77,2907.75) C10.2@-316.77,2939.75
NetC13_1: C13.1 C15.2 L2.2 | length 594.2
  Top Layer w31.5: v1@-656.77,2570.09 -656.77,2647.24 cw(c-608.97,2647.24) -642.77,2681.04 -636.77,2687.03 cw(c-566.06,2616.32) -566.06,2716.32 -506.75,2716.32 ccw(c-506.75,2784.61) -458.47,2736.32 -451.03,2743.76 ccw(c-512.02,2804.74) -425.77,2804.74 v1(-425.77,2907.32)
  Bottom Layer w10: L2.2 -683.99,2570.09 C13.1@-625.81,2570.09
  Bottom Layer w31.5: v1(-425.77,2907.32) C15.2@-425.77,2939.32
  other v1: -659.77,2570.09
NetC14_1: C14.1 C15.1 C17.1 R12.2 | length 143.8
  Bottom Layer w31.5: R12.2 -578.91,2983.29 -576.94,2983.29 R12.2@-572.91,2987.32 ; R12.2@-565.91,2987.32 C15.1@-431.77,2987.32
NetL1_1: L1.1 U1.11 | length 637.8
  Top Layer w8: v1(-780.77,2514.32) -732.03,2465.58 -449.51,2465.58 -325.77,2589.32 v1(-325.77,2624.32)
  Bottom Layer w8: v1(-780.77,2514.32) -748.88,2514.32 L1.1 ; v1(-325.77,2624.32) -323.38,2624.32 -324.24,2623.46 -324.24,2620.63 -322.44,2618.82 -322.44,2590.07 U1.11
NetL2_1: L2.1 U1.13 | length 754.6
  Top Layer w8: v1(-783.77,2580.32) -687.02,2483.57 -453.52,2483.57 -349.77,2587.32 -349.77,2632.32 -323.77,2658.32 -292.97,2658.32 v1(-268.97,2634.32)
  Bottom Layer w8: v1(-783.77,2580.32) -749.35,2580.32 L2.1 ; U1.13 -282.11,2621.19 v1(-268.97,2634.32)
NetR1_1: R1.1 U1.9 | length 131.4
  Bottom Layer w8: -390.44,2589.93 -361.32,2589.57 U1.9
  Bottom Layer w15: R1.1 -462.12,2602.67 -449.07,2589.71 -390.44,2589.93
NetR2_2: R2.2 U1.28 | length 111.9
  Bottom Layer w8: U1.28 -282.11,2342.92 -248.65,2309.45 -248.65,2292.36 R2.2
NetR3_2: R3.2 U1.29 | length 101.2
  Bottom Layer w8: U1.29 -301.79,2328.05 -294.97,2321.23 -294.97,2293.03 R3.2
NetR4_2: R4.2 U1.30 | length 107.2
  Bottom Layer w8: R4.2 -342.97,2292.78 -342.97,2308.78 -321.48,2330.28 U1.30
NetR8_1: R8.1 U1.32 | length 193.3
  Bottom Layer w8: R8.1@-485.12,2277.43 R8.1 -445.96,2275.57 -421.97,2299.56 -421.97,2317.24 -360.85,2378.36 U1.32
NetR9_1: R9.1 U1.1 | length 162.3
  Bottom Layer w8: R9.1 -443.18,2323.57 -391.52,2375.24 U1.1
NetR10_1: R10.1 U1.7 | length 110
  Bottom Layer w8: R10.1 -472.95,2503.57 -437.77,2538.75 U1.7
NetR11_1: R11.1 U1.8 | length 102.7
  Bottom Layer w8: R11.1@-486.75,2558.44 U1.8 ; R11.1 R11.1@-481.45,2554.27
NetR13_1: R13.1 U1.6 | length 130
  Bottom Layer w8: R13.1 -480.74,2465.58 -462.94,2465.58 -454.44,2474.09 -454.44,2491.09 -426.3,2519.23 -391.68,2519.23 U1.6
NetR14_1: R14.1 U1.31 | length 118.5
  Bottom Layer w8: R14.1 -388.97,2293.33 -388.97,2309.48 -341.16,2357.29 U1.31
NetR15_1: R15.1 U1.24 | length 403.4
  Bottom Layer w8: U1.24 -192.39,2375.61 -220,2348 -220,2229 -194,2203 -89,2203 -66.47,2225.53 R15.1@-66.47,2252.22
NetTP2_1: TP2.1 U1.23 | length 94.4
  Bottom Layer w8: U1.23 -161.18,2440.33 -141.97,2421.12 TP2.1
NFC_INT: J1.12 J2.12 | length 8314.9
  Top Layer w8: J2.12@-5.91,5756.81 v1(-5.91,5324.23) -5.91,4343.88 ccw(c94.09,4343.88) 23.38,4273.17 30.23,4266.32 ccw(c83.34,4319.44) 83.34,4244.32 1088.26,4244.32 cw(c1088.26,4203.35) 1117.23,4232.32 cw(c1095.5,4210.59) 1126.23,4210.59 1126.23,4098.32 1126.23,2561.74 cw(c1026.23,2561.74) 1096.94,2491.03 667.52,2061.61 cw(c596.81,2132.32) 596.81,2032.32 213.22,2032.32 ccw(c213.22,1932.32) 142.51,2003.03 114.53,1975.06 ccw(c185.25,1904.35) 85.25,1904.35 85.25,1866.57 236.22,649.15 v1(236.22,511.32) J1.12@236.22,78.74
  Bottom Layer w8: v1(-5.91,5324.23) J2.12@-5.91,5756.81 ; J1.12@236.22,78.74 v1(236.22,511.32)
PWM1: J1.4 J2.4 | length 8317.8
  Top Layer w8: J2.4@-163.39,5756.81 v1(-163.39,5324.23) -163.39,4297.36 ccw(c-63.39,4297.36) -134.1,4226.65 -51.06,4143.61 ccw(c19.65,4214.32) 19.65,4114.32 963.67,4114.32 cw(c963.67,4076.77) 990.23,4103.32 cw(c970.92,4084.01) 998.23,4084.01 998.23,4039.32 998.23,2621.74 cw(c898.23,2621.74) 968.94,2551.03 612.52,2194.61 cw(c541.81,2265.32) 541.81,2165.32 143.65,2165.32 ccw(c143.65,2065.32) 72.94,2136.03 -45.28,2017.82 ccw(c25.43,1947.11) -74.57,1947.11 -74.57,1885.37 78.74,649.15 v1(78.74,511.32) J1.4@78.74,78.74
  Bottom Layer w8: v1(-163.39,5324.23) J2.4@-163.39,5756.81 ; J1.4@78.74,78.74 v1(78.74,511.32)
PWM2: J1.3 J2.3 | length 8282.8
  Top Layer w8: J2.3@-183.07,5756.81 v1(-183.07,5340.23) -183.07,4293.35 ccw(c-83.07,4293.35) -153.78,4222.64 -57.76,4126.61 ccw(c12.95,4197.32) 12.95,4097.32 945.67,4097.32 cw(c945.67,4059.77) 972.23,4086.32 cw(c948.09,4062.18) 982.23,4062.18 982.23,4035.32 982.23,2628.74 cw(c882.23,2628.74) 952.94,2558.03 606.09,2211.19 cw(c535.38,2281.9) 535.38,2181.9 135.9,2181.9 ccw(c135.9,2081.9) 65.19,2152.61 -65.33,2022.09 ccw(c5.38,1951.38) -94.62,1951.38 -94.62,1888.34 59.06,649.15 v1(59.06,495.32) J1.3@59.06,78.74
  Bottom Layer w8: v1(-183.07,5340.23) J2.3@-183.07,5756.81 ; J1.3@59.06,78.74 v1(59.06,495.32)
SCL: J1.15 J2.15 R14.2 | length 9135.3
  Top Layer w8: v1(53.1,5340.28) 53.1,4342.84 ccw(c104.75,4342.84) 68.23,4306.32 ccw(c102.03,4340.12) 102.03,4292.32 1157.33,4292.32 cw(c1157.33,4268.42) 1174.2,4285.35 cw(c1162.16,4273.25) 1179.23,4273.25 1179.23,4098.32 1179.23,2543.74 cw(c1079.23,2543.74) 1149.94,2473.03 687.52,2010.61 cw(c616.81,2081.32) 616.81,1981.32 247.65,1981.32 ccw(c247.65,1881.32) 176.94,1952.03 170.23,1945.32 ccw(c230.82,1884.73) 145.13,1884.73 145.13,1858.31 295.08,649.15 v1@295.08,495.32 ; v1(53.1,5340.28) J2.15@53.15,5756.81 ; J1.15@295.28,78.74 295.28,478.28 295.23,478.32 v1(295.23,495.28) v1@295.28,495.32
  Bottom Layer w8: R14.2 -390.4,2236.34 ccw(c-336.63,2236.34) -374.65,2198.32 ccw(c-348.09,2224.88) -348.09,2187.32 99.5,2187.32 cw(c99.5,2156.59) 121.23,2178.32 cw(c60.87,2117.97) 146.23,2117.97 v1(146.23,1902.32) ; v1(53.1,5340.28) 53.1,5357.23 ; 53.15,5357.28 J2.15@53.15,5756.81 ; v1(295.23,495.28) 295.23,478.32 295.28,478.28 J1.15@295.28,78.74
SDA: J1.16 J2.16 R15.2 | length 8836.6
  Top Layer w8: J2.16@72.83,5756.81 v1(72.83,5324.23) 72.83,4337.59 ccw(c101.49,4337.59) 81.23,4317.32 ccw(c105.37,4341.46) 105.37,4307.32 1166.09,4307.32 cw(c1166.09,4273.18) 1190.23,4297.32 cw(c1175.74,4282.84) 1196.23,4282.84 1196.23,4098.32 1196.23,2538.74 cw(c1096.23,2538.74) 1166.94,2468.03 693.52,1994.61 cw(c622.81,2065.32) 622.81,1965.32 254,1965.32 ccw(c254,1876.55) 191.23,1939.32 ccw(c254,1876.55) 165.23,1876.55 165.23,1856.57 314.96,649.15 v1(314.96,511.32) J1.16@314.96,78.74
  Bottom Layer w8: R15.2@-27.1,2252.22 102.6,2252.22 cw(c102.6,2187.69) 148.23,2233.32 cw(c95.12,2180.21) 170.23,2180.21 v1(170.23,1906.32) ; v1(72.83,5324.23) J2.16@72.83,5756.81 ; J1.16@314.96,78.74 v1(314.96,511.32)
SPR_GPO1: J1.9 J2.9 | length 8275.6
  Top Layer w8: J2.9@-64.96,5756.81 v1(-64.96,5340.23) -64.96,4325.61 ccw(c35.04,4325.61) -35.67,4254.9 -4.39,4223.61 ccw(c66.32,4294.32) 66.32,4194.32 1030.6,4194.32 cw(c1030.6,4139.7) 1069.23,4178.32 cw(c1052.33,4161.42) 1076.23,4161.42 1076.23,4098.32 1076.23,2586.74 cw(c976.23,2586.74) 1046.94,2516.03 641.52,2110.61 cw(c570.81,2181.32) 570.81,2081.32 185.94,2081.32 ccw(c185.94,1981.32) 115.23,2052.03 54.96,1991.76 ccw(c125.67,1921.05) 25.67,1921.05 25.67,1869.17 176.97,649.15 v1@176.97,495.32 ; J1.9@177.17,78.74 v1(177.17,495.32)
  Bottom Layer w8: v1(-64.96,5340.23) J2.9@-64.96,5756.81 ; J1.9@177.17,78.74 v1(177.17,495.32)
SPR_GPO2: J1.6 J2.6 | length 8315.2
  Top Layer w8: J2.6@-124.02,5756.81 v1(-124.02,5324.23) -124.02,4309.99 ccw(c-24.02,4309.99) -94.73,4239.28 -32.06,4176.61 ccw(c38.65,4247.32) 38.65,4147.32 992.26,4147.32 cw(c992.26,4106.35) 1021.23,4135.32 cw(c1001.92,4116.01) 1029.23,4116.01 1029.23,4039.32 1029.23,2608.74 cw(c929.23,2608.74) 999.94,2538.03 622.52,2160.61 cw(c551.81,2231.32) 551.81,2131.32 156.4,2131.32 ccw(c156.4,2031.32) 85.69,2102.03 -5.28,2011.06 ccw(c65.43,1940.35) -34.57,1940.35 -34.57,1880.35 118.11,649.15 v1(118.11,511.32) J1.6@118.11,78.74
  Bottom Layer w8: v1(-124.02,5324.23) J2.6@-124.02,5756.81 ; J1.6@118.11,78.74 v1(118.11,511.32)
TOFINT: J1.13 J2.13 | length 8286.2
  Top Layer w8: J2.13@13.78,5756.81 v1(13.78,5340.23) 13.78,4351 ccw(c110.91,4351) 42.23,4282.32 ccw(c92.93,4333.02) 92.93,4261.32 1115.91,4261.32 cw(c1115.91,4234.01) 1135.23,4253.32 cw(c1113.5,4231.59) 1144.23,4231.59 1144.23,4098.32 1144.23,2553.74 cw(c1044.23,2553.74) 1114.94,2483.03 676.52,2044.61 cw(c605.81,2115.32) 605.81,2015.32 226.65,2015.32 ccw(c226.65,1915.32) 155.94,1986.03 134.28,1964.37 ccw(c204.99,1893.66) 104.99,1893.66 104.99,1864.54 255.71,649.15 v1@255.71,495.32 ; J1.13@255.91,78.74 v1(255.91,495.32)
  Bottom Layer w8: v1(13.78,5340.23) J2.13@13.78,5756.81 ; J1.13@255.91,78.74 v1(255.91,495.32)
VMID: C8.1 R5.1 U1.16 | length 227.7
  Bottom Layer w8: U1.16 -223.05,2592.68 -220.95,2594.78 -200.97,2594.78
  Bottom Layer w17: C8.1 -100.33,2556.95 -100.33,2539.17 -90.37,2529.21 -72.78,2529.21 -62.78,2519.21 -62.78,2500.78 R5.1
  Bottom Layer w20: -200.97,2594.78 -161.83,2594.78 v1(-133.44,2566.39) -129.12,2562.07 -105.45,2562.07 C8.1
pads on no net: U1.19 U1.20 U1.25 U1.26 U1.27

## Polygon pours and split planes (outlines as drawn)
GND on Top Layer "GND TOP" (hatched 45Degree grid 30 track 9.5, remove dead copper, pour order 1): -1284.09,1874.98 -149.22,1874.98 0,647.51 0,0 413.39,0 413.39,647.51 264.16,1874.98 622.68,1874.98 1236.22,2488.52 1236.22,4401.3 171.26,4401.3 171.26,5807.99 -242.13,5807.99 -242.13,4401.3 -1897.64,4401.3 -1897.64,2649.98 -1897.64,2488.52
no net on Top Layer "3.3V Input Top" (solid, pour order 0): -1897.64,4401.3

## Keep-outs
Keep-Out Layer:
  lines w0.5: -1897.64,2488.52 -1284.09,1874.98 -149.22,1874.98 0,647.51 0,0 413.39,0 413.39,647.51 264.16,1874.98 622.68,1874.98 1236.22,2488.52 1236.22,2649.98 1236.22,4401.3 171.26,4401.3 171.26,5807.99 -242.13,5807.99 -242.13,4401.3 -1897.64,4401.3 -1897.64,2649.98 -1897.64,2488.52

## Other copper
Top Layer:
  rectangle net 3V3: 107.1,4343.32 129.1,5652.77
  rectangle net +5: 137.1,4376.32 162.1,5658.23
  region net GND: 12.23,639.52 41.74,643.14 -112.41,1898.58 -141.92,1894.95
  region net 3V3: 349.43,643.65 371.23,646.32 224.31,1842.91 202.51,1840.23
  region net +5: 380.23,649.15 404.5,652.13 257.78,1847.04 233.51,1844.06
  rectangle net +5: 379.23,177.32 404.23,656.32
  rectangle net 3V3: 349.23,179.32 371.23,647.51
  pour cut-out: 900,4000.34 -1650,4000.34 -1650,2647.24 900,2647.24
  pour cut-out: 0,167.32 413.39,167.32 413.39,0 0,0
  pour cut-out: -242.13,5807.99 171.26,5807.99 171.26,5697.32 -242.13,5697.32
Bottom Layer:
  rectangle net 3V3: -155,2277.43 27,2296
  rectangle net 3V3: 108.23,5303.32 129.1,5652.77
  rectangle net 3V3: 28.23,5215.32 129.23,5275.32
  rectangle net 3V3: 108.23,5215.32 129.23,5331.32
  rectangle net 3V3: 28.23,4261.32 90.23,5275.32
  rectangle net +5: 134.23,4333.32 1073.23,4384.32
  rectangle net +5: 110.23,4333.32 162.1,5202.32
  rectangle net +5: 137.1,4359.32 162.1,5658.23
  region net 3V3: 349.43,643.65 371.23,646.32 212.93,1935.51 191.14,1932.84
  region net +5: 380.23,649.15 404.5,652.13 250.77,1904.11 226.5,1901.13
  rectangle net +5: 379.23,177.32 404.23,656.32
  rectangle net 3V3: 349.23,179.32 371.23,647.51
  pour cut-out: 900,4000.34 -1650,4000.34 -1650,2647.24 900,2647.24
  pour cut-out: 900,4000
  pour cut-out: -242.13,5807.99 171.26,5807.99 171.26,5697.32 -242.13,5697.32
  pour cut-out: 0,0 0,167.32 413.39,167.32 413.39,0

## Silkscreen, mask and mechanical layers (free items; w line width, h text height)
Bottom Overlay:
  circle w12: c19.19,179.32 r4
  circle w12: c-222.44,5680 r4
  text "J2" at -170.94,5641.63 h28
  text "J1" at 59.06,195.02 h28
Mechanical 1:
  drawing of 4185 lines, arcs and shapes, not listed
  text "6" at -8257.75,8935.67 h121.11
  text "5" at -4714.44,8935.67 h121.11
  text "4" at -1171.14,8935.67 h121.11
  text "3" at 2372.17,8935.67 h121.11
  text "2" at 5915.48,8935.67 h121.11
  text "1" at 9458.78,8935.67 h121.11
  text "APPD/DATE" at 10961.6,8600.58 h80.74
  text "ZONE" at 5503.39,8598 h80.74
  text "ECN" at 4615.22,8594.98 h80.74
  text "ISSUE" at 5059.3,8594.98 h80.74
  text "DESCRIPTION" at 7537.46,8594.98 h80.74
  text "DRN/DATE" at 9744.62,8594.98 h80.74
  text "CHK/DATE" at 10357.48,8594.98 h80.74
  text "NOTE: THIS DRAWING WAS PRODUCED BY COMPUTER, DO NOT UPDATE MANUALLY" at -9830.97,8445.99 h157.48
  text "E" at -10164.08,7258.26 h121.11
  text "E" at 11441.56,7258.26 h121.11
  text "9,35" at 4843.99,5722.02 h137.8
  text "R0,4" at -4856.45,5404.16 h137.8 r322.13
  text "R0,4" at -4626.96,5378.75 h137.8 r28.27
  text "R0,4" at -5087.06,5218.79 h137.8 r49.62
  text "1,9" at 6129.49,5033.55 h137.8 r90
  text "18,3" at 6738.51,4873.89 h137.8 r90
  text "R0,4" at -4376.37,4654.34 h137.8 r346.55
  text "R1,5" at -4461.89,4357.65 h137.8 r297.71
  text "5,7" at 4886.95,4328.17 h137.8
  text "D" at -10164.08,4266.13 h121.11
  text "D" at 11441.56,4266.13 h121.11
  text "10,6" at 549.29,4108.34 h137.8
  text "42,2" at 6737.64,3683 h137.8 r90
  text "3,2" at 5261.14,3227.38 h137.8
  text "R1,5" at -4705.17,3190.89 h137.8 r52.37
  text "R1,7" at -4609.69,3004.08 h137.8 r19.46
  text "56" at 6729.88,1749.93 h137.8 r90
  text "C" at -10175.61,1274.01 h121.11
  text "C" at 11441.56,1274.01 h121.11
  text "~}" at -650.45,1222.04 h137.8
  text "R1,7" at -4486.74,800.93 h137.8 r337.84
  text "R1,7" at -4706.1,793.81 h137.8 r324.73
  text "3,2" at 5023.28,669.9 h137.8
  text "R0,4" at -4626.03,529.28 h137.8 r323.84
  text "2" at 5109.04,96.57 h137.8
  text "6" at 6727.8,91.17 h137.8 r90
  text "B" at -10164.08,-1718.12 h121.11
  text "B" at 11441.56,-1718.12 h121.11
  text "Coremi Industries Co., Limited" at 6767,-4537.45 h196.85
  text "T10" at 10697.06,-4685.77 h137.8
  text "A" at -10198.68,-4710.25 h121.11
  text "A" at 11441.56,-4710.25 h121.11
  text "REVISION NO." at 9712.4,-4724.51 h99.5
  text "DRAWING NO." at 6765,-4791.45 h99.5
  text "Airzai-041T10" at 8009,-4814.45 h137.8
  text "Airzai" at 9887.08,-4876.56 h137.8
  text "MODEL :" at 9239.96,-4960.73 h99.5
  text "MANIFOLD_SOLID_BREP_27740" at 7315,-5004.45 h98.43
  text "TITLE:" at 6751,-5006.45 h99.5
  text "METERIAL:" at 6759.64,-5196.95 h99.5
  text "MASS :                 kg" at 9239.96,-5196.95 h99.5
  text "1" at 8513.77,-5395.56 h137.8
  text "P/N:" at 9239.96,-5423.87 h118.11
  text "FINISH:" at 6759.64,-5433.18 h99.5
  text "QTY:" at 8039.17,-5433.18 h99.5
  text "NOTE:" at -9288.44,-5516.69 h118.11
  text ".  TOLERANCES  ." at 8008.35,-5597.63 h79.6
  text "1:1" at 7291.68,-5623.26 h137.8
  text "1.UNSPECIFIED DRAFT ANGLE 1.0\Fgdt;{\Fgdt;~}" at -9288.44,-5635.98 h118.11
  text "SCALE:" at 6759.64,-5669.4 h99.5
  text "DRN.DATE" at 9239.96,-5669.4 h99.5
  text "Daniel Apr/20,2019" at 9893.41,-5693.33 h118.11
  text "All dimensions are in mm" at 8001.97,-5728.69 h59.7
  text "\Ftxt;2.UNSPECIFIED FILLET TO BE R0.3" at -9288.44,-5755.27 h118.11
  text "Daniel Apr/20,201" at 9893.41,-5812.62 h118.11
  text "unless otherwise specified." at 8011.53,-5837.06 h59.7
  text "A2" at -9917.08,-5900.87 h236.22
  text "PROJECTION" at 6759.64,-5905.62 h99.5
  text "CHK.DATE" at 9239.96,-5905.62 h99.5
  text "X" at 8303.78,-5933.41 h59.7
  text "0.20" at 8710.88,-5933.41 h59.7
  text ".X" at 8303.78,-6020.22 h59.7
  text "0.10" at 8710.88,-6020.22 h59.7
  text ".XX" at 8303.78,-6107.03 h59.7
  text "0.05" at 8710.88,-6107.03 h59.7
  text "1  1" at 7277.53,-6131.32 h137.8
  text "SHEET   OF" at 6759.64,-6141.84 h99.5
  text "APP.DATE" at 9239.96,-6141.84 h99.5
  text "ANGLE" at 8288.44,-6193.84 h59.7
  text "~}" at 8710.88,-6193.84 h59.7
  text "6" at -8257.75,-6417.7 h121.11
  text "5" at -4714.44,-6417.7 h121.11
  text "4" at -1171.14,-6417.7 h121.11
  text "3" at 2372.17,-6417.7 h121.11
  text "2" at 5915.48,-6417.7 h121.11
  text "1" at 9458.78,-6417.7 h121.11
Mechanical 2:
  rectangle: -242.13,5667.13 171.26,5807.99
  rectangle: 0,0 413.39,176.52
  lines w0.5: 7548.99,-5931.56 7731.73,-5931.56 ; 7640.36,-6022.92 7640.36,-5840.19 ; 7690.91,-5932.21 7978.71,-5932.21
  lines w8: -2150,2990 -1750,2990 ccw(c-1750,3110.71) -1664.64,3025.36 -60.95,4629.05 ccw(c-146.3,4714.41) -25.59,4714.41 -25.59,5650 ; -1800,2990 -1720,2990 cw(c-1720,2869.29) -1634.64,2954.64 164.64,1155.36 cw(c79.29,1070) 200,1070 200,190 ; -25.59,5650 -10.19,5634.6 cw(c-34.79,5610) 0,5610 -50,5610 cw(c-12.36,5610) -38.98,5636.61 -25.59,5650 ; 200,190 213.39,203.39 ccw(c186.77,230) 224.41,230 174.41,230 ccw(c209.2,230) 184.6,205.4 200,190
  text "Stiffener Location" at -2700,2975.32 h30
Mechanical 4:
  lines w0.5: -1897.64,2488.52 -1897.64,2649.98 -1897.64,4401.3 -242.13,4401.3 -242.13,5807.99 171.26,5807.99 171.26,4401.3 1236.22,4401.3 1236.22,2649.98 1236.22,2488.52 622.68,1874.98 264.16,1874.98 413.39,647.51 413.39,0 0,0 0,647.51 -149.22,1874.98 -1284.09,1874.98 -1897.64,2488.52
